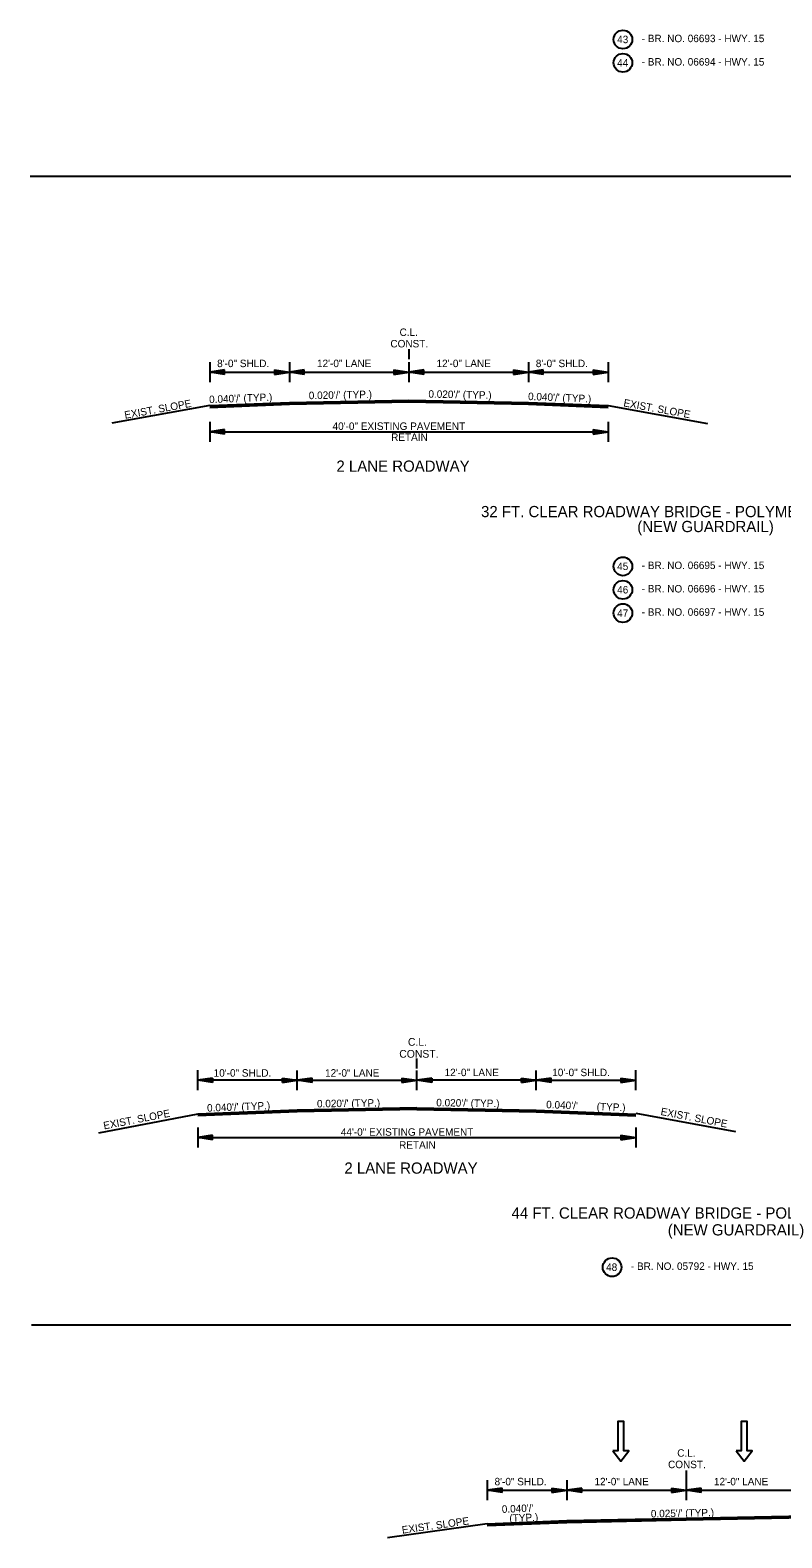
# Model space of a CAD drawing. Extents: x 545241 to 1930787, y -1971772 to 596640.
# Drawn here: x 546719 to 547474, y -1968762 to -1967249 of the extents above; entities that cross this region are included whole.
import ezdxf

# ---------------------------------------------------------------- set-up
doc = ezdxf.new("R2010")
doc.units = 0
doc.layers.add('R_Border', color=7, linetype='Continuous')
doc.layers.add('R_Draft', color=7, linetype='Continuous')

# ---------------------------------------------------------------- blocks, each defined once
blk = doc.blocks.new('ARROW')
at = {"layer": 'R_Draft'}
for p, q in [((-2, 0.3), (0, 0)), ((-2, 0.3), (-2, -0.3)), ((-2, 0.25), (-0.334, 0)), ((-2, 0.199), (-0.678, 0)), ((-2, 0.149), (-1.011, 0)), ((-2, 0.097), (-1.35, 0)), ((-2, 0.047), (-1.684, 0)), ((-2, -0.3), (0, 0)), ((-2, -0.098), (-1.35, 0)), ((-2, -0.199), (-0.678, 0)), ((-2, -0.25), (-0.334, 0)), ((-2, -0.149), (-1.011, 0)), ((-2, -0.047), (-1.684, 0))]:
    blk.add_line(p, q, dxfattribs=at)

msp = doc.modelspace()

# ---------------------------------------------------------------- linework, layer by layer
at = {"layer": 'R_Border'}
for p, q in [((546718.9, -1967395.3), (547746.9, -1967395.3)), ((547099.2, -1967569), (547099.2, -1967579)), ((546899.2, -1967582), (546899.2, -1967602)), ((546899.2, -1967592), (547299.2, -1967592)), ((546979.2, -1967582), (546979.2, -1967602)), ((547099.2, -1967582), (547099.2, -1967602)), ((547219.2, -1967582), (547219.2, -1967602)), ((547299.2, -1967582), (547299.2, -1967602)), ((546899.2, -1967625.6), (546801, -1967643.3)), ((547299.2, -1967625.6), (547399.2, -1967643.6)), ((546899.2, -1967642), (546899.2, -1967662)), ((546899.2, -1967652), (547299.2, -1967652)), ((547299.2, -1967642), (547299.2, -1967662)), ((546987.2, -1968332.8), (546887.2, -1968336.8)), ((546987.2, -1968333.1), (546887.2, -1968337.1)), ((546987.2, -1968333.4), (546887.2, -1968337.4)), ((546987.2, -1968333.7), (546887.2, -1968337.7)), ((546987.2, -1968334), (546887.2, -1968338)), ((547227.2, -1968332.8), (547327.2, -1968336.8)), ((547227.2, -1968333.1), (547327.2, -1968337.1)), ((547227.2, -1968333.4), (547327.2, -1968337.4)), ((547227.2, -1968333.7), (547327.2, -1968337.7)), ((547227.2, -1968334), (547327.2, -1968338)), ((546987.2, -1968334.3), (546887.2, -1968338.3)), ((546987.2, -1968334.5), (546887.2, -1968338.5)), ((547227.2, -1968334.3), (547327.2, -1968338.3)), ((547227.2, -1968334.5), (547327.2, -1968338.5)), ((546720.3, -1968548.2), (547748.2, -1968548.2)), ((547377.8, -1968694.4), (547377.8, -1968704.4)), ((547177.8, -1968704.4), (547177.8, -1968724.4)), ((547257.8, -1968704.4), (547257.8, -1968724.4)), ((547377.8, -1968704.4), (547377.8, -1968724.4)), ((547177.8, -1968714.4), (547577.8, -1968714.4)), ((547177.8, -1968748), (547077.9, -1968762.1))]:
    msp.add_line(p, q, dxfattribs=at)
for points in [[(546899.2, -1967625.6), (546979.2, -1967622.4), (547099.2, -1967620), (547219.2, -1967622.4), (547299.2, -1967625.6)], [(546899.2, -1967625.9), (546979.2, -1967622.7), (547099.2, -1967620.3), (547219.2, -1967622.7), (547299.2, -1967625.9)], [(546899.2, -1967626.2), (546979.2, -1967623), (547099.2, -1967620.6), (547219.2, -1967623), (547299.2, -1967626.2)], [(546899.2, -1967626.5), (546979.2, -1967623.3), (547099.2, -1967620.9), (547219.2, -1967623.3), (547299.2, -1967626.5)], [(546899.2, -1967626.8), (546979.2, -1967623.6), (547099.2, -1967621.2), (547219.2, -1967623.6), (547299.2, -1967626.8)], [(546899.2, -1967627.1), (546979.2, -1967623.9), (547099.2, -1967621.5), (547219.2, -1967623.9), (547299.2, -1967627.1)], [(546899.2, -1967627.4), (546979.2, -1967624.2), (547099.2, -1967621.8), (547219.2, -1967624.2), (547299.2, -1967627.4)], [(547177.8, -1968748), (547257.8, -1968744.8), (547377.8, -1968742.4), (547497.8, -1968740), (547577.8, -1968738.4)], [(547177.8, -1968748.3), (547257.8, -1968745.1), (547377.8, -1968742.7), (547497.8, -1968740.3), (547577.8, -1968738.7)], [(547177.8, -1968748.6), (547257.8, -1968745.4), (547377.8, -1968743), (547497.8, -1968740.6), (547577.8, -1968739)], [(547177.8, -1968748.9), (547257.8, -1968745.7), (547377.8, -1968743.3), (547497.8, -1968740.9), (547577.8, -1968739.3)], [(547177.8, -1968749.2), (547257.8, -1968746), (547377.8, -1968743.6), (547497.8, -1968741.2), (547577.8, -1968739.6)], [(547177.8, -1968749.5), (547257.8, -1968746.3), (547377.8, -1968743.9), (547497.8, -1968741.5), (547577.8, -1968739.9)], [(547177.8, -1968749.8), (547257.8, -1968746.6), (547377.8, -1968744.2), (547497.8, -1968741.8), (547577.8, -1968740.2)]]:
    msp.add_lwpolyline(points, dxfattribs=at)
for points in [[(547304.2, -1968674.7), (547312.2, -1968685.1), (547320.2, -1968674.7), (547315.2, -1968674.7), (547315.1, -1968645.3), (547309.1, -1968645.3), (547309.2, -1968674.7)], [(547427.9, -1968674.7), (547435.9, -1968685.1), (547443.9, -1968674.7), (547438.9, -1968674.7), (547438.9, -1968645.3), (547432.9, -1968645.3), (547432.9, -1968674.7)]]:
    msp.add_lwpolyline(points, close=True, dxfattribs=at)
for centre in [(547314.2, -1967258.1), (547314.2, -1967281.5), (547314.2, -1967787), (547314.2, -1967810.5), (547314.2, -1967833.9), (547303.3, -1968490.5)]:
    msp.add_circle(centre, 9.34, dxfattribs=at)
at = {"layer": 'R_Draft'}
for p, q in [((547107.2, -1968291.1), (547107.2, -1968281.1)), ((546887.2, -1968312.8), (546887.2, -1968292.8)), ((546902.2, -1968300.6), (546887.2, -1968302.8)), ((546987.2, -1968302.8), (546887.2, -1968302.8)), ((546902.2, -1968305.1), (546887.2, -1968302.8)), ((546902.2, -1968301), (546889.7, -1968302.8)), ((546902.2, -1968304.7), (546889.7, -1968302.8)), ((546902.2, -1968301.3), (546892.3, -1968302.8)), ((546902.2, -1968304.3), (546892.3, -1968302.8)), ((546902.2, -1968301.7), (546894.8, -1968302.8)), ((546902.2, -1968304), (546894.8, -1968302.8)), ((546902.2, -1968302.1), (546897.4, -1968302.8)), ((546902.2, -1968303.6), (546897.4, -1968302.8)), ((546902.2, -1968302.5), (546899.9, -1968302.8)), ((546902.2, -1968303.2), (546899.9, -1968302.8)), ((546902.2, -1968300.6), (546902.2, -1968305.1)), ((546972.2, -1968300.6), (546987.2, -1968302.8)), ((546972.2, -1968305.1), (546972.2, -1968300.6)), ((546972.2, -1968301), (546984.7, -1968302.8)), ((546972.2, -1968301.3), (546982.2, -1968302.8)), ((546972.2, -1968301.7), (546979.7, -1968302.8)), ((546972.2, -1968302.1), (546977.1, -1968302.8)), ((546972.2, -1968302.5), (546974.6, -1968302.8)), ((546972.2, -1968305.1), (546987.2, -1968302.8)), ((546972.2, -1968303.6), (546977.1, -1968302.8)), ((546972.2, -1968304.3), (546982.2, -1968302.8)), ((546972.2, -1968304.7), (546984.7, -1968302.8)), ((546972.2, -1968304), (546979.7, -1968302.8)), ((546972.2, -1968303.2), (546974.6, -1968302.8)), ((546987.2, -1968312.8), (546987.2, -1968292.9)), ((547002.2, -1968300.6), (546987.2, -1968302.8)), ((547002.2, -1968305.1), (546987.2, -1968302.8)), ((546987.2, -1968302.8), (547107.2, -1968302.8)), ((547002.2, -1968301), (546989.7, -1968302.8)), ((547002.2, -1968304.7), (546989.7, -1968302.8)), ((547002.2, -1968301.3), (546992.3, -1968302.8)), ((547002.2, -1968304.3), (546992.3, -1968302.8)), ((547002.2, -1968301.7), (546994.8, -1968302.8)), ((547002.2, -1968304), (546994.8, -1968302.8)), ((547002.2, -1968302.1), (546997.4, -1968302.8)), ((547002.2, -1968303.6), (546997.4, -1968302.8)), ((547002.2, -1968302.5), (546999.9, -1968302.8)), ((547002.2, -1968303.2), (546999.9, -1968302.8)), ((547002.2, -1968305.1), (547002.2, -1968300.6)), ((547092.2, -1968300.6), (547107.2, -1968302.8)), ((547092.2, -1968300.6), (547092.2, -1968305.1)), ((547092.2, -1968301), (547104.7, -1968302.8)), ((547092.2, -1968301.3), (547102.2, -1968302.8)), ((547092.2, -1968301.7), (547099.7, -1968302.8)), ((547092.2, -1968302.1), (547097.1, -1968302.8)), ((547092.2, -1968302.5), (547094.6, -1968302.8)), ((547092.2, -1968305.1), (547107.2, -1968302.8)), ((547092.2, -1968303.6), (547097.1, -1968302.8)), ((547092.2, -1968304.3), (547102.2, -1968302.8)), ((547092.2, -1968304.7), (547104.7, -1968302.8)), ((547092.2, -1968304), (547099.7, -1968302.8)), ((547092.2, -1968303.2), (547094.6, -1968302.8)), ((547107.2, -1968312.8), (547107.2, -1968292.9)), ((547122.2, -1968300.6), (547107.2, -1968302.8)), ((547227.2, -1968302.8), (547107.2, -1968302.8)), ((547122.2, -1968305.1), (547107.2, -1968302.8)), ((547122.2, -1968301), (547109.7, -1968302.8)), ((547122.2, -1968304.7), (547109.7, -1968302.8)), ((547122.2, -1968301.3), (547112.3, -1968302.8)), ((547122.2, -1968304.3), (547112.3, -1968302.8)), ((547122.2, -1968301.7), (547114.8, -1968302.8)), ((547122.2, -1968304), (547114.8, -1968302.8)), ((547122.2, -1968302.1), (547117.4, -1968302.8)), ((547122.2, -1968303.6), (547117.4, -1968302.8)), ((547122.2, -1968302.5), (547119.9, -1968302.8)), ((547122.2, -1968303.2), (547119.9, -1968302.8)), ((547122.2, -1968300.6), (547122.2, -1968305.1)), ((547212.2, -1968300.6), (547227.2, -1968302.8)), ((547212.2, -1968305.1), (547212.2, -1968300.6)), ((547212.2, -1968301), (547224.7, -1968302.8)), ((547212.2, -1968301.3), (547222.2, -1968302.8)), ((547212.2, -1968301.7), (547219.7, -1968302.8)), ((547212.2, -1968302.1), (547217.1, -1968302.8)), ((547212.2, -1968302.5), (547214.6, -1968302.8)), ((547212.2, -1968305.1), (547227.2, -1968302.8)), ((547212.2, -1968303.6), (547217.1, -1968302.8)), ((547212.2, -1968304.3), (547222.2, -1968302.8)), ((547212.2, -1968304.7), (547224.7, -1968302.8)), ((547212.2, -1968304), (547219.7, -1968302.8)), ((547212.2, -1968303.2), (547214.6, -1968302.8)), ((547227.2, -1968312.8), (547227.2, -1968292.9)), ((547242.2, -1968300.6), (547227.2, -1968302.8)), ((547227.2, -1968302.8), (547327.2, -1968302.8)), ((547242.2, -1968305.1), (547227.2, -1968302.8)), ((547242.2, -1968301), (547229.7, -1968302.8)), ((547242.2, -1968304.7), (547229.7, -1968302.8)), ((547242.2, -1968301.3), (547232.3, -1968302.8)), ((547242.2, -1968304.3), (547232.3, -1968302.8)), ((547242.2, -1968301.7), (547234.8, -1968302.8)), ((547242.2, -1968304), (547234.8, -1968302.8)), ((547242.2, -1968302.1), (547237.4, -1968302.8)), ((547242.2, -1968303.6), (547237.4, -1968302.8)), ((547242.2, -1968302.5), (547239.9, -1968302.8)), ((547242.2, -1968303.2), (547239.9, -1968302.8)), ((547242.2, -1968305.1), (547242.2, -1968300.6)), ((547312.2, -1968300.6), (547327.2, -1968302.8)), ((547312.2, -1968300.6), (547312.2, -1968305.1)), ((547312.2, -1968301), (547324.7, -1968302.8)), ((547312.2, -1968301.3), (547322.2, -1968302.8)), ((547312.2, -1968301.7), (547319.7, -1968302.8)), ((547312.2, -1968302.1), (547317.1, -1968302.8)), ((547312.2, -1968302.5), (547314.6, -1968302.8)), ((547312.2, -1968305.1), (547327.2, -1968302.8)), ((547312.2, -1968303.6), (547317.1, -1968302.8)), ((547312.2, -1968304.3), (547322.2, -1968302.8)), ((547312.2, -1968304.7), (547324.7, -1968302.8)), ((547312.2, -1968304), (547319.7, -1968302.8)), ((547312.2, -1968303.2), (547314.6, -1968302.8)), ((547327.2, -1968312.8), (547327.2, -1968292.8)), ((547107.2, -1968330.4), (546987.2, -1968332.8)), ((547107.2, -1968330.7), (546987.2, -1968333.1)), ((547107.2, -1968331), (546987.2, -1968333.4)), ((547107.3, -1968331.3), (546987.2, -1968333.7)), ((547107.3, -1968331.6), (546987.2, -1968334)), ((547107.3, -1968331.9), (546987.2, -1968334.3)), ((547107.3, -1968332.1), (546987.2, -1968334.5)), ((547107.2, -1968330.4), (547227.2, -1968332.8)), ((547107.2, -1968330.7), (547227.2, -1968333.1)), ((547107.2, -1968331), (547227.2, -1968333.4)), ((547107.2, -1968331.3), (547227.2, -1968333.7)), ((547107.2, -1968331.6), (547227.2, -1968334)), ((547107.2, -1968331.9), (547227.2, -1968334.3)), ((547107.2, -1968332.1), (547227.2, -1968334.5)), ((546887.2, -1968336.8), (546787.5, -1968355.9)), ((547327.2, -1968336), (547427.3, -1968354.4)), ((546887.2, -1968350.3), (546887.2, -1968370.3)), ((546902.2, -1968358.1), (546887.2, -1968360.3)), ((546887.2, -1968360.3), (547327.2, -1968360.3)), ((546902.2, -1968362.6), (546887.2, -1968360.3)), ((546902.2, -1968358.4), (546889.7, -1968360.3)), ((546902.2, -1968362.2), (546889.7, -1968360.3)), ((546902.2, -1968358.8), (546892.3, -1968360.3)), ((546902.2, -1968361.8), (546892.3, -1968360.3)), ((546902.2, -1968359.2), (546894.8, -1968360.3)), ((546902.2, -1968361.4), (546894.8, -1968360.3)), ((546902.2, -1968359.6), (546897.4, -1968360.3)), ((546902.2, -1968361), (546897.4, -1968360.3)), ((546902.2, -1968359.9), (546899.9, -1968360.3)), ((546902.2, -1968360.7), (546899.9, -1968360.3)), ((546902.2, -1968362.6), (546902.2, -1968358.1)), ((547312.2, -1968358.1), (547327.2, -1968360.3)), ((547312.2, -1968358.1), (547312.2, -1968362.6)), ((547312.2, -1968358.4), (547324.7, -1968360.3)), ((547312.2, -1968358.8), (547322.2, -1968360.3)), ((547312.2, -1968359.2), (547319.7, -1968360.3)), ((547312.2, -1968359.6), (547317.1, -1968360.3)), ((547312.2, -1968359.9), (547314.6, -1968360.3)), ((547312.2, -1968362.6), (547327.2, -1968360.3)), ((547312.2, -1968361), (547317.1, -1968360.3)), ((547312.2, -1968361.8), (547322.2, -1968360.3)), ((547312.2, -1968362.2), (547324.7, -1968360.3)), ((547312.2, -1968361.4), (547319.7, -1968360.3)), ((547312.2, -1968360.7), (547314.6, -1968360.3)), ((547327.2, -1968350.3), (547327.2, -1968370.3))]:
    msp.add_line(p, q, dxfattribs=at)

# ---------------------------------------------------------------- block references
at = {"layer": 'R_Border', "xscale": 7.5, "yscale": 7.5, "rotation": 180}
for p in [(546899.2, -1967592), (546979.2, -1967592), (547099.2, -1967592), (547219.2, -1967592), (546899.2, -1967652), (547177.8, -1968714.4), (547257.8, -1968714.4), (547377.8, -1968714.4)]:
    msp.add_blockref('ARROW', p, dxfattribs=at)
at = {"layer": 'R_Border', "xscale": 7.5, "yscale": 7.5}
for p in [(546979.2, -1967592), (547099.2, -1967592), (547219.2, -1967592), (547299.2, -1967592), (547299.2, -1967652), (547257.8, -1968714.4), (547377.8, -1968714.4)]:
    msp.add_blockref('ARROW', p, dxfattribs=at)

# ---------------------------------------------------------------- texts
at = {"layer": 'R_Border'}
for s, height, p in [('CONST.', 7.5, (547080.7, -1967567.2)), ('C.L.', 7.5, (547089.9, -1967555.7)), ('8\'-0" SHLD.', 7.5, (546906.7, -1967587)), ('12\'-0" LANE', 7.5, (547007, -1967587)), ('12\'-0" LANE', 7.5, (547127, -1967587)), ('8\'-0" SHLD.', 7.5, (547226.7, -1967587)), ('40\'-0" EXISTING PAVEMENT', 7.5, (547022.6, -1967650)), ('RETAIN', 7.5, (547081.4, -1967661)), ('2 LANE ROADWAY', 11.25, (547026.5, -1967692)), ('32 FT. CLEAR ROADWAY BRIDGE - POLYMER OVERLAY', 11.25, (547171.7, -1967737.6)), ('(NEW GUARDRAIL)', 11.25, (547328.6, -1967752.6)), ('C.L.', 7.5, (547368.7, -1968680.7)), ('CONST.', 7.5, (547359.5, -1968692.2)), ('8\'-0" SHLD.', 7.5, (547185.3, -1968709.4)), ('12\'-0" LANE', 7.5, (547285.6, -1968709.4)), ('12\'-0" LANE', 7.5, (547405.6, -1968709.4))]:
    msp.add_text(s, height=height, dxfattribs=at).set_placement(p)
for s, rotation, p in [('EXIST. SLOPE', 10.204, (546814.3, -1967638.9)), ("0.040'/' (TYP.)", 2.2916, (546898.8, -1967623.2)), ("0.020'/' (TYP.)", 1.1458, (546998.8, -1967619.2)), ("0.020'/' (TYP.)", 358.8542, (547118.8, -1967617.6)), ("0.040'/' (TYP.)", 357.7084, (547218.8, -1967620)), ('EXIST. SLOPE', 349.796, (547314.3, -1967626.3)), ('EXIST. SLOPE', 7.9696, (547092.7, -1968758)), ("0.040'/'", 2.2916, (547192.7, -1968737.1)), ('(TYP.)', 2.2916, (547200.3, -1968746.2)), ("0.025'/' (TYP.)", 1.1458, (547342.3, -1968741.7))]:
    msp.add_text(s, height=7.5, rotation=rotation, dxfattribs=at).set_placement(p)
at = {"layer": 'R_Draft'}
for s, height, p in [('43', 7.5, (547308.4, -1967261.8)), ('- BR. NO. 06693 - HWY. 15', 7.5, (547333, -1967260.8)), ('44', 7.5, (547308.4, -1967285.3)), ('- BR. NO. 06694 - HWY. 15', 7.5, (547333, -1967284.3)), ('45', 7.5, (547308.4, -1967790.7)), ('- BR. NO. 06695 - HWY. 15', 7.5, (547333, -1967789.7)), ('46', 7.5, (547308.4, -1967814.2)), ('- BR. NO. 06696 - HWY. 15', 7.5, (547333, -1967813.2)), ('47', 7.5, (547308.4, -1967837.7)), ('- BR. NO. 06697 - HWY. 15', 7.5, (547333, -1967836.6)), ('CONST.', 7.8, (547089.6, -1968280.2)), ('C.L.', 7.8, (547098.3, -1968268.2)), ('10\'-0" SHLD.', 7.5, (546903.2, -1968299.2)), ('12\'-0" LANE', 7.5, (547015.1, -1968299.2)), ('12\'-0" LANE', 7.5, (547135.1, -1968298.7)), ('10\'-0" SHLD.', 7.5, (547243.2, -1968298.7)), ('44\'-0" EXISTING PAVEMENT', 7.5, (547030.9, -1968358.5)), ('RETAIN', 7.5, (547089.4, -1968371.5)), ('2 LANE ROADWAY', 11.25, (547034.5, -1968396.6)), ('44 FT. CLEAR ROADWAY BRIDGE - POLYMER OVERLAY', 11.25, (547202.3, -1968441.7)), ('(NEW GUARDRAIL)', 11.25, (547359.2, -1968458.6)), ('48', 7.5, (547297.3, -1968494.2)), ('- BR. NO. 05792 - HWY. 15', 7.5, (547322.2, -1968493.2))]:
    msp.add_text(s, height=height, dxfattribs=at).set_placement(p)
for s, rotation, p in [('EXIST. SLOPE', 10.8829, (546793.2, -1968352.2)), ("0.040'/' (TYP.)", 2.2906, (546896.7, -1968334.4)), ("0.020'/' (TYP.)", 0.8719, (547007, -1968330.1)), ("0.020'/' (TYP.)", 359.1281, (547126.7, -1968328.9)), ("0.040'/' ", 357.7094, (547237, -1968330.8)), ('(TYP.)', 357.7094, (547287.7, -1968332.8)), ('EXIST. SLOPE', 349.1171, (547351.6, -1968337.6))]:
    msp.add_text(s, height=7.5, rotation=rotation, dxfattribs=at).set_placement(p)

doc.saveas('drawing.dxf')
